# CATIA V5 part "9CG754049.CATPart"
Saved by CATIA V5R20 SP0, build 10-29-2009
Part number: 9CG754049
Revision: ANY
Definition: UNKNOWN
Nomenclature: 9CG754049
Source: Unknown
Bounding box of the stored display mesh (mm): x -30 to 45, y -29 to 27, z -20 to 20
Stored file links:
  C:\Users\Utente\Desktop\IO LAVORO\3D X SITO CF\CUMSA\3D files CG\CG 754049\9CG754049.CATPart
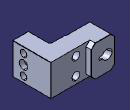
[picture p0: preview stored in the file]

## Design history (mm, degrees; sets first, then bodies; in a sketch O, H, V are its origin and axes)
Body1 "Cortar-Extruir3" (main body)
  Solid1: solid without history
